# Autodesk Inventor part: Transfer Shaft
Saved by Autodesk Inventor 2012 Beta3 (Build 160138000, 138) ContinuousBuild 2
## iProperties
Created: 2011-01
Part Number: Transfer Shaft
Material: Steel
Document SubType Name: Modeling
Designer: Beta-8540w
Density: 1 g/cm^3
CustomPartVersion: 1
Author: Beta-8540w
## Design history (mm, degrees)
sketch "Main Sketch"
  geometry: L1 (0, 0)-(51, 0) reference; L2 (0, 0)-(0, 5); L3 (0, 5)-(10, 5); L4 (10, 5)-(10, 6); L5 (10, 6)-(13, 6); L6 (13, 6)-(13, 12.5); L7 (25, 12.5)-(25, 6); L8 (13, 12.5)-(25, 12.5); L9 (41, 6)-(41, 5); L10 (25, 6)-(41, 6); L11 (51, 5)-(51, 0); L12 (41, 5)-(51, 5)
  constraints: 24 end point, 7 horizontal, 6 vertical
  dimensions: "d3" = 10 diameter of L3 L1 (derived); "d4" = 12 diameter of L5 L1 (derived); "d5" = 25 diameter of L8 L1 (derived); "d6" = 12 diameter of L10 L1 (derived); "d7" = 10 diameter of L12 L1 (derived)
revolve "Revolution1" sketch "Main Sketch" stored, may be unused: angle "d8" = 0 deg
chamfer "Chamfer1" distance "d9" = 0.3; stored, may be unused: second distance "d10" = 0.125, angle "d11" = 45 deg
chamfer "Chamfer2" distance "d12" = 0.3; stored, may be unused: second distance "d13" = 0.125, angle "d14" = 45 deg
node "Spur Gear Teeth1"
node "Keyway1"
body "Solid1"
feature "Spur Gear1"
feature "Shaft Keyway"
other parameters: "d0" = 0, "d1" = 0, "d2" = 0
